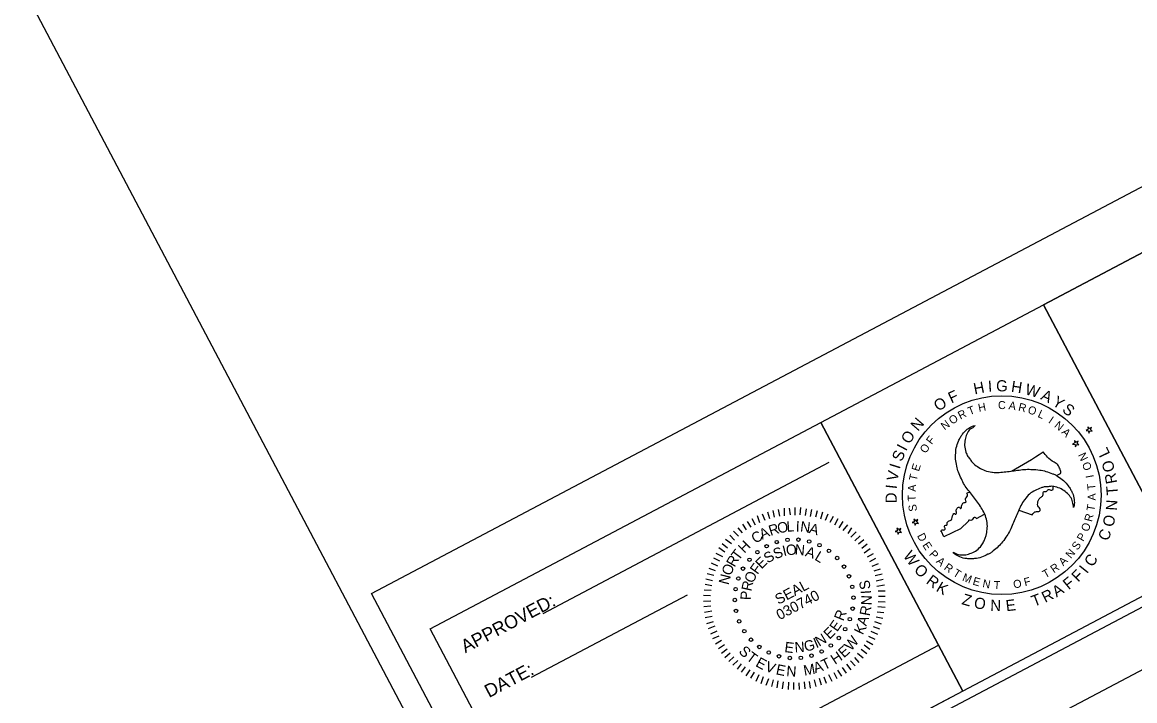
# Model space of a CAD drawing. Extents: x 1485914 to 1489436, y 493744 to 499689.
# Drawn here: x 1488661 to 1489164, y 498560 to 498867 of the extents above; entities that cross this region are included whole.
import ezdxf

# ---------------------------------------------------------------- set-up
doc = ezdxf.new("R2010")
doc.units = 0
for name, color, linetype in [('DEV BORDER CELL', 7, 'Continuous'), ('DEV DOT SWIRL SEAL CELL', 7, 'Continuous'), ('Old_Level_9', 7, 'Continuous'), ('Scratch_Level_0', 7, 'Continuous'), ('Scratch_Level_6', 7, 'Continuous'), ('Sheet Plot Border Outside CELL', 7, 'Continuous'), ('Sheet Sticker Exception Certification CELL', 7, 'Continuous'), ('Text', 7, 'Continuous'), ('WZ OSDR CELL', 7, 'Continuous')]:
    doc.layers.add(name, color=color, linetype=linetype)

msp = doc.modelspace()

# ---------------------------------------------------------------- linework, layer by layer
at = {"layer": 'DEV BORDER CELL'}
for p, q in [((1488896.29, 498599.43), (1489025.69, 498667.76)), ((1489032.96, 498665.02), (1489086.19, 498564.21)), ((1488891.04, 498570.56), (1488961.6, 498607.82))]:
    msp.add_line(p, q, dxfattribs=at)
for points in [[(1488911.97, 499654.77), (1487585.52, 498954.38), (1488075.8, 498025.87), (1489402.24, 498726.26)], [(1489331.49, 498849.23), (1489122.8, 498739.03), (1489187.01, 498617.44), (1489395.7, 498727.63)], [(1489021.99, 498685.8), (1489122.8, 498739.03), (1489187.01, 498617.44), (1489086.19, 498564.21)], [(1488845.1, 498592.4), (1489021.99, 498685.8), (1489086.19, 498564.21), (1488909.3, 498470.8)]]:
    msp.add_lwpolyline(points, close=True, dxfattribs=at)
at = {"layer": 'DEV DOT SWIRL SEAL CELL'}
for p, q in [((1489142.96, 498682.73), (1489142, 498682.22)), ((1489143.56, 498683.05), (1489142.77, 498683.77)), ((1489142.77, 498683.77), (1489142.96, 498682.73)), ((1489144.52, 498683.56), (1489143.56, 498683.05)), ((1489144.04, 498682.57), (1489144.52, 498683.56)), ((1489144.81, 498681.8), (1489144.04, 498682.57)), ((1489137.48, 498676.85), (1489136.69, 498677.56)), ((1489136.69, 498677.56), (1489136.87, 498676.53)), ((1489142, 498682.22), (1489143.08, 498682.07)), ((1489143.08, 498682.07), (1489143.28, 498681)), ((1489143.28, 498681), (1489143.73, 498681.96)), ((1489143.73, 498681.96), (1489144.81, 498681.8)), ((1489136.87, 498676.53), (1489135.91, 498676.02)), ((1489135.91, 498676.02), (1489136.99, 498675.87)), ((1489136.99, 498675.87), (1489137.2, 498674.79)), ((1489137.2, 498674.79), (1489137.64, 498675.75)), ((1489138.43, 498677.35), (1489137.48, 498676.85)), ((1489137.64, 498675.75), (1489138.72, 498675.6)), ((1489137.95, 498676.37), (1489138.43, 498677.35)), ((1489138.72, 498675.6), (1489137.95, 498676.37)), ((1489092.36, 498642.39), (1489096.1, 498644.33)), ((1489111.56, 498646.17), (1489117.55, 498644.06)), ((1489057.21, 498637.29), (1489056.42, 498638.01)), ((1489056.42, 498638.01), (1489056.61, 498636.98)), ((1489058.17, 498637.8), (1489057.21, 498637.29)), ((1489057.69, 498636.82), (1489058.17, 498637.8)), ((1489057.69, 498636.82), (1489058.17, 498637.8)), ((1489064.29, 498641.02), (1489063.33, 498640.51)), ((1489063.33, 498640.51), (1489064.41, 498640.35)), ((1489064.89, 498641.33), (1489064.1, 498642.05)), ((1489064.1, 498642.05), (1489064.29, 498641.02)), ((1489064.41, 498640.35), (1489064.61, 498639.28)), ((1489064.61, 498639.28), (1489065.06, 498640.24)), ((1489065.85, 498641.84), (1489064.89, 498641.33)), ((1489065.06, 498640.24), (1489066.14, 498640.09)), ((1489065.37, 498640.86), (1489065.85, 498641.84)), ((1489066.14, 498640.09), (1489065.37, 498640.86)), ((1489085.23, 498637.66), (1489077.66, 498634.02)), ((1489088.82, 498641.16), (1489085.23, 498637.66)), ((1489056.61, 498636.98), (1489055.65, 498636.47)), ((1489055.65, 498636.47), (1489056.73, 498636.31)), ((1489056.73, 498636.31), (1489056.93, 498635.24)), ((1489056.93, 498635.24), (1489057.38, 498636.2)), ((1489057.38, 498636.2), (1489058.46, 498636.05)), ((1489057.38, 498636.2), (1489058.46, 498636.05)), ((1489058.46, 498636.05), (1489057.69, 498636.82)), ((1489058.46, 498636.05), (1489057.69, 498636.82)), ((1489077.66, 498634.02), (1489076.5, 498636.41))]:
    msp.add_line(p, q, dxfattribs=at)
for start, end in [(299.0386, 303.1587), (293.5136, 293.8113)]:
    msp.add_arc((1488995.05, 498867.66), 233.19, start, end, dxfattribs=at)
for points in [[(1489081.81, 498627.04), (1489084.3, 498626.08), (1489086.87, 498625.86), (1489089.38, 498626.45), (1489091.95, 498627.63), (1489094.18, 498629.56), (1489095.41, 498631.3), (1489095.82, 498632.25), (1489096.54, 498633.88), (1489096.92, 498635.29), (1489097.29, 498638.15), (1489097.12, 498641.23), (1489096.11, 498644.3), (1489096, 498644.55), (1489094.58, 498647.2), (1489092.8, 498649.69), (1489091.06, 498652.08), (1489089.17, 498654.51), (1489087.34, 498656.94), (1489085.92, 498659.51), (1489084.52, 498662.56), (1489083.61, 498665.33), (1489083.06, 498668.38), (1489082.86, 498669.85), (1489082.95, 498671.17), (1489083.25, 498674.33), (1489084.27, 498677.3), (1489085.07, 498679), (1489085.98, 498680.33), (1489086.13, 498680.56), (1489088.22, 498682.7), (1489090.64, 498684.1), (1489091.58, 498684.32)], [(1489091.61, 498684.43), (1489091.58, 498684.32), (1489089.53, 498682.69), (1489088.03, 498680.53), (1489087.29, 498678.08), (1489087.03, 498675.3), (1489087.6, 498672.38), (1489088.47, 498670.44), (1489089.11, 498669.63), (1489090.15, 498668.17), (1489091.16, 498667.13), (1489093.49, 498665.41), (1489096.21, 498664), (1489099.41, 498663.35), (1489099.67, 498663.31), (1489102.64, 498663.2), (1489105.73, 498663.5), (1489108.65, 498663.83), (1489111.68, 498664.25), (1489114.72, 498664.57), (1489117.66, 498664.54), (1489121, 498664.25), (1489123.84, 498663.65), (1489126.75, 498662.61), (1489128.15, 498662.04), (1489129.24, 498661.28), (1489131.84, 498659.47), (1489133.89, 498657.09), (1489134.98, 498655.54), (1489135.69, 498654.09), (1489135.81, 498653.85), (1489136.58, 498650.95), (1489136.57, 498648.15), (1489136.32, 498647.26)], [(1489128.57, 498661.77), (1489130.61, 498663.19), (1489130.03, 498665.09), (1489129.28, 498666.55), (1489127.5, 498667.75), (1489124.53, 498670.11), (1489122.59, 498672.45)], [(1489076.5, 498636.41), (1489076.3, 498636.6), (1489076.57, 498637.06), (1489077.91, 498637.19), (1489078.21, 498637.95), (1489077.93, 498638.41), (1489078.13, 498639.13), (1489078.96, 498639.37), (1489079.19, 498640.58), (1489079.72, 498641.08), (1489081.04, 498641.78), (1489081.79, 498644.19), (1489082.38, 498644.63), (1489082.78, 498644.3), (1489083.22, 498644.43), (1489083.24, 498646.1), (1489083.32, 498646.37), (1489084.25, 498647.5), (1489084.71, 498647.43), (1489085.11, 498646.9), (1489085.34, 498646.9), (1489085.6, 498647.38), (1489085.78, 498648.37), (1489086.5, 498649.42), (1489087.73, 498649.88), (1489087.42, 498650.94), (1489088.3, 498652.55), (1489088.29, 498653.24), (1489088.07, 498653.83)], [(1489136.32, 498647.26), (1489135.92, 498649.84), (1489134.83, 498652.21), (1489133.04, 498654.09), (1489130.76, 498655.71), (1489127.98, 498656.67), (1489125.86, 498656.88), (1489124.82, 498656.73), (1489123.07, 498656.6), (1489121.61, 498656.19), (1489118.98, 498655.07), (1489116.38, 498653.4), (1489114.24, 498650.96), (1489114.07, 498650.75), (1489112.51, 498648.2), (1489111.21, 498645.42), (1489110, 498642.71), (1489108.86, 498639.87), (1489107.65, 498637.04), (1489106.15, 498634.54), (1489104.2, 498631.79), (1489102.27, 498629.64), (1489099.92, 498627.65), (1489098.72, 498626.71), (1489097.53, 498626.14), (1489094.68, 498624.82), (1489091.57, 498624.21), (1489089.71, 498624.05), (1489088.09, 498624.19), (1489087.81, 498624.2), (1489084.92, 498624.95), (1489082.52, 498626.35), (1489081.81, 498627.04)], [(1489117.55, 498644.06), (1489118.81, 498645.3), (1489120.31, 498645.48), (1489120.96, 498645.7), (1489121.27, 498646.34), (1489120.12, 498648.13), (1489120.09, 498649.23), (1489121.32, 498651.8), (1489122.43, 498652.74), (1489122.74, 498654.37), (1489123.13, 498654.55), (1489123.88, 498654.52), (1489125.02, 498655.45), (1489126.48, 498655.16), (1489127.05, 498655.53), (1489127.04, 498656.72)], [(1489092.36, 498642.39), (1489091.75, 498642.8), (1489091.06, 498642.66), (1489090.46, 498641.8), (1489089.85, 498641.51), (1489088.91, 498641.65), (1489088.82, 498641.16)]]:
    msp.add_spline(points, degree=3, dxfattribs=at)
at = {"layer": 'Old_Level_9'}
for p, q in [((1489010.12, 498647.25), (1489010.2, 498643.9)), ((1489012.81, 498647.25), (1489012.43, 498643.95)), ((1488990.77, 498642.4), (1488992.29, 498639.53)), ((1488993.09, 498643.63), (1488994.28, 498640.58)), ((1488995.37, 498644.41), (1488996.55, 498641.64)), ((1488997.86, 498645.3), (1488998.71, 498642.36)), ((1489000.2, 498645.97), (1489000.83, 498642.91)), ((1489002.65, 498646.41), (1489003.28, 498643.35)), ((1489005.32, 498646.98), (1489005.39, 498643.62)), ((1489007.67, 498647.08), (1489008.01, 498644.02)), ((1489015.33, 498646.75), (1489014.84, 498643.67)), ((1489017.8, 498646.36), (1489017.2, 498643.21)), ((1489020.33, 498645.86), (1489019.61, 498642.93)), ((1489022.64, 498645.24), (1489021.76, 498642.09)), ((1489025.12, 498644.28), (1489023.95, 498641.41)), ((1489027.49, 498643.27), (1489025.98, 498640.5)), ((1488984.38, 498638.18), (1488986.33, 498635.82)), ((1488986.53, 498639.74), (1488988.15, 498637.2)), ((1488988.57, 498640.96), (1488990.3, 498638.48)), ((1489029.64, 498642.15), (1489028.13, 498639.38)), ((1489031.85, 498640.91), (1489030.17, 498638.19)), ((1489034, 498639.51), (1489031.99, 498636.89)), ((1489035.88, 498638.09), (1489034.15, 498635.48)), ((1488978.79, 498632.97), (1488981.52, 498631.02)), ((1488980.76, 498634.86), (1488982.94, 498632.61)), ((1488982.51, 498636.63), (1488984.75, 498634.28)), ((1489037.99, 498636.24), (1489035.58, 498633.84)), ((1489039.76, 498634.49), (1489037.41, 498632.26)), ((1489041.42, 498632.68), (1489038.95, 498630.67)), ((1488975.86, 498629.16), (1488978.58, 498627.21)), ((1488977.38, 498631.09), (1488979.72, 498629.08)), ((1489042.86, 498630.76), (1489040.5, 498628.8)), ((1489044.31, 498628.55), (1489041.61, 498626.7)), ((1488972.26, 498622.31), (1488975.26, 498620.92)), ((1488973.33, 498624.57), (1488976.16, 498623.24)), ((1488974.46, 498626.72), (1488977.4, 498625.17)), ((1489045.65, 498626.29), (1489042.88, 498624.83)), ((1489046.76, 498624.19), (1489043.99, 498622.73)), ((1488970.58, 498617.47), (1488973.56, 498616.64)), ((1488971.25, 498619.94), (1488974.13, 498618.78)), ((1489047.87, 498621.81), (1489045.1, 498620.63)), ((1489048.88, 498619.37), (1489045.93, 498618.52)), ((1489049.65, 498617.09), (1489046.48, 498616.41)), ((1488969.57, 498612.69), (1488972.6, 498612.03)), ((1488969.85, 498615.1), (1488972.94, 498614.33)), ((1489050.21, 498614.7), (1489047.04, 498614.02)), ((1489050.71, 498612.14), (1489047.31, 498611.62)), ((1488968.84, 498607.64), (1488972.03, 498607.49)), ((1488969.12, 498610.05), (1488972.31, 498609.9)), ((1489051, 498609.46), (1489047.86, 498609.51)), ((1489051.1, 498607.12), (1489048.03, 498607.05)), ((1488968.84, 498604.96), (1488972.2, 498605.03)), ((1488969.01, 498602.5), (1488972.25, 498602.8)), ((1489051.05, 498602.14), (1489047.69, 498602.35)), ((1489051.11, 498604.43), (1489047.86, 498604.7)), ((1488969.24, 498599.93), (1488972.58, 498600.57)), ((1488969.68, 498597.48), (1488972.85, 498598.17)), ((1489050.04, 498597.09), (1489047.01, 498597.75)), ((1489050.54, 498599.61), (1489047.4, 498599.93)), ((1488970.35, 498594.87), (1488973.41, 498595.78)), ((1488971.13, 498592.6), (1488974.07, 498593.72)), ((1489048.64, 498592.25), (1489045.82, 498593.3)), ((1489049.43, 498594.5), (1489046.33, 498595.55)), ((1488972.14, 498590.16), (1488975.07, 498591.57)), ((1488973.13, 498588), (1488976.01, 498589.24)), ((1488974.36, 498585.68), (1488977.01, 498587.36)), ((1489046.56, 498587.61), (1489043.73, 498588.95)), ((1489047.8, 498589.82), (1489044.69, 498591.15)), ((1488975.64, 498583.53), (1488978.34, 498585.38)), ((1488977.03, 498581.43), (1488979.56, 498583.33)), ((1489042.79, 498581.1), (1489040.17, 498583.11)), ((1489044.14, 498583.09), (1489041.59, 498584.99)), ((1489045.55, 498585.24), (1489042.61, 498586.8)), ((1488978.53, 498579.4), (1488980.94, 498581.52)), ((1488980.3, 498577.65), (1488982.6, 498579.71)), ((1488982.18, 498575.95), (1488984.42, 498578.13)), ((1489037.49, 498575.62), (1489035.42, 498577.92)), ((1489039.35, 498577.17), (1489037.29, 498579.47)), ((1489041.16, 498579.11), (1489038.59, 498581.29)), ((1488984.23, 498574.21), (1488986.08, 498576.6)), ((1488986.11, 498572.8), (1488987.9, 498575.3)), ((1488988.21, 498571.22), (1488990.05, 498573.89)), ((1488990.25, 498570.04), (1488991.92, 498572.76)), ((1488992.74, 498568.81), (1488994.02, 498571.74)), ((1489029.4, 498569.79), (1489027.94, 498572.55)), ((1489031.44, 498571.01), (1489029.7, 498573.77)), ((1489033.53, 498572.4), (1489031.8, 498574.87)), ((1489035.68, 498573.95), (1489033.67, 498576.43)), ((1488995, 498567.74), (1488996.05, 498570.84)), ((1488997.25, 498566.95), (1488998.36, 498569.94)), ((1488999.84, 498566.34), (1489000.5, 498569.37)), ((1489002.15, 498565.72), (1489002.69, 498568.97)), ((1489004.67, 498565.21), (1489005.1, 498568.41)), ((1489007.3, 498565.05), (1489007.46, 498568.24)), ((1489009.77, 498564.94), (1489009.75, 498568.18)), ((1489012.28, 498564.99), (1489012.21, 498568.07)), ((1489014.85, 498565.22), (1489014.55, 498568.45)), ((1489017.36, 498565.55), (1489016.84, 498568.67)), ((1489019.91, 498566.34), (1489019.06, 498569.28)), ((1489022.3, 498566.89), (1489021.4, 498569.95)), ((1489024.58, 498567.67), (1489023.51, 498570.5)), ((1489027.02, 498568.67), (1489025.61, 498571.61))]:
    msp.add_line(p, q, dxfattribs=at)
for centre in [(1489002.01, 498631.67), (1489006.87, 498632.68), (1489011.82, 498632.78), (1489016.71, 498631.96), (1488993.26, 498627.09), (1488997.43, 498629.79), (1489021.37, 498630.26), (1489025.64, 498627.74), (1488989.67, 498623.68), (1489029.36, 498624.47), (1488986.76, 498619.67), (1489032.43, 498620.58), (1488984.64, 498615.19), (1489034.73, 498616.19), (1489036.18, 498611.45), (1488983.38, 498610.39), (1489036.73, 498606.52), (1488983.02, 498605.45), (1489036.37, 498601.58), (1488983.58, 498600.53), (1489035.11, 498596.78), (1488985.03, 498595.79), (1488987.33, 498591.39), (1489032.99, 498592.3), (1488990.39, 498587.5), (1489030.08, 498588.29), (1488994.12, 498584.23), (1488998.39, 498581.71), (1489022.33, 498582.19), (1489026.49, 498584.88), (1489003.04, 498580.01), (1489007.93, 498579.2), (1489012.89, 498579.3), (1489017.74, 498580.3)]:
    msp.add_circle(centre, 0.788, dxfattribs=at)
at = {"layer": 'Scratch_Level_0'}
msp.add_lwpolyline([(1488891.1, 499587.21), (1487653.08, 498933.51), (1488096.67, 498093.43), (1488873.83, 498503.79), (1488818.61, 498608.38), (1489279.46, 498851.72)], close=True, dxfattribs=at)
at = {"layer": 'Scratch_Level_6'}
msp.add_lwpolyline([(1489122.8, 498739.03), (1489331.49, 498849.23), (1489395.7, 498727.63), (1489187.01, 498617.44)], close=True, dxfattribs=at)
at = {"layer": 'Sheet Plot Border Outside CELL'}
msp.add_lwpolyline([(1487943.33, 497927.66), (1489436.02, 498715.83), (1488922.4, 499688.55), (1487429.71, 498900.38)], close=True, dxfattribs=at)
at = {"layer": 'Sheet Sticker Exception Certification CELL'}
for p, q in [((1488898.33, 498491.59), (1489075.22, 498584.99)), ((1489075.23, 498584.98), (1489086.2, 498564.2)), ((1489086.19, 498564.21), (1488909.3, 498470.8))]:
    msp.add_line(p, q, dxfattribs=at)
at = {"layer": 'Text'}
msp.add_circle((1489103.82, 498652.91), 44.97, dxfattribs=at)
at = {"layer": 'WZ OSDR CELL'}
msp.add_lwpolyline([(1487648.11, 498943.96), (1488414.63, 499348.7), (1488845.5, 498532.69), (1488078.98, 498127.95)], close=True, dxfattribs=at)

# ---------------------------------------------------------------- texts
at = {"layer": 'DEV BORDER CELL'}
for s, p in [('APPROVED:  ', (1488861.08, 498581.33)), ('DATE:  ', (1488871.78, 498561.07))]:
    msp.add_text(s, height=6, rotation=27.8351, dxfattribs=at).set_placement(p)
at = {"layer": 'DEV DOT SWIRL SEAL CELL'}
for s, height, rotation, p in [('H', 5.04, 11.2891, (1489091.58, 498698.45)), ('I', 5.04, 3.6391, (1489097.75, 498699.6)), ('G', 5.04, 359.3518, (1489101.26, 498699.88)), ('H', 5.04, 351.2983, (1489107.86, 498699.7)), ('W', 5.04, 343.6484, (1489114.05, 498698.66)), ('F', 5.04, 25.0926, (1489081.04, 498694.35)), ('A', 5.04, 334.6113, (1489121.11, 498696.4)), ('Y', 5.04, 327.5835, (1489126.3, 498693.88)), ('O', 5.04, 33.6, (1489075.15, 498690.61)), ('H', 3.63, 11.4673, (1489093.53, 498690.53)), ('C', 3.63, 1.3112, (1489102.18, 498691.8)), ('A', 3.63, 351.155, (1489106.79, 498691.83)), ('R', 3.63, 346.0769, (1489111.08, 498691.2)), ('O', 3.63, 340.9988, (1489115.27, 498690.12)), ('S', 5.04, 321.06, (1489130.81, 498691)), ('N', 5.04, 49.4212, (1489065.93, 498681.52)), ('O', 3.63, 31.7797, (1489081.28, 498684.72)), ('R', 3.63, 26.7016, (1489085.11, 498687.06)), ('L', 3.63, 335.9207, (1489119.83, 498688.38)), ('I', 3.63, 325.7646, (1489124.63, 498685.82)), ('N', 3.63, 36.8577, (1489077.95, 498682.15)), ('N', 3.63, 320.6865, (1489127.33, 498683.96)), ('A', 3.63, 315.6084, (1489130.64, 498681.12)), ('O', 5.04, 57.9286, (1489062.1, 498675.69)), ('F', 3.63, 52.092, (1489072.13, 498675.56)), ('S', 5.04, 68.4199, (1489058.63, 498667.81)), ('I', 5.04, 62.2159, (1489060.51, 498672.55)), ('O', 3.63, 57.1701, (1489069.51, 498671.51)), ('N', 3.63, 115.5681, (1489143.06, 498669.49)), ('O', 3.63, 110.762, (1489144.78, 498664.89)), ('V', 5.04, 79.4157, (1489056.6, 498659.03)), ('I', 5.04, 72.7073, (1489057.64, 498664.44)), ('T', 3.63, 77.4824, (1489065.33, 498659.14)), ('E', 3.63, 72.4043, (1489066.32, 498663.4)), ('I', 5.04, 83.703, (1489056.27, 498655.53)), ('A', 3.63, 87.6386, (1489064.93, 498654.42)), ('I', 3.63, 100.6058, (1489145.57, 498661.06)), ('T', 3.63, 95.5277, (1489146.33, 498655.36)), ('D', 5.04, 91.2941, (1489056.34, 498649.3)), ('T', 3.63, 92.7167, (1489064.99, 498650.16)), ('A', 3.63, 90.4496, (1489146.38, 498650.48)), ('S', 3.63, 97.7948, (1489065.52, 498645.75)), ('T', 3.63, 80.2935, (1489145.71, 498645.44)), ('R', 3.63, 75.2154, (1489144.58, 498640.61)), ('O', 3.63, 70.1373, (1489142.98, 498636.08)), ('D', 3.63, 298.1071, (1489065.39, 498634.54)), ('P', 3.63, 59.9811, (1489140.69, 498631.68)), ('E', 3.63, 303.1852, (1489067.77, 498630.3)), ('P', 3.63, 313.3414, (1489070.73, 498625.98)), ('N', 3.63, 49.825, (1489135.09, 498624)), ('S', 3.63, 54.903, (1489138.12, 498627.72)), ('A', 3.63, 318.4194, (1489073.87, 498622.6)), ('R', 3.63, 323.4975, (1489077.38, 498619.54)), ('A', 3.63, 44.7469, (1489131.69, 498620.63)), ('T', 3.63, 328.5756, (1489081.45, 498616.71)), ('M', 3.63, 338.7318, (1489085.68, 498614.31)), ('T', 3.63, 29.5126, (1489123.55, 498615.18)), ('R', 3.63, 34.5907, (1489127.41, 498617.49)), ('E', 3.63, 343.8099, (1489090.41, 498612.5)), ('N', 3.63, 348.8879, (1489094.91, 498611.3)), ('T', 3.63, 359.0441, (1489100.18, 498610.42)), ('O', 3.63, 9.2003, (1489109.32, 498610.7)), ('F', 3.63, 14.2784, (1489114.36, 498611.69))]:
    msp.add_text(s, height=height, rotation=rotation, dxfattribs=at).set_placement(p)
at = {"layer": 'Old_Level_9'}
for s, height, rotation, p in [('A', 4.72, 25.81, (1488995.46, 498632.72)), ('R', 4.72, 17.8566, (1488999.22, 498634.43)), ('O', 4.72, 10.9219, (1489002.72, 498635.57)), ('L', 4.72, 3.581, (1489006.56, 498636.32)), ('I', 4.72, 358.641, (1489010.59, 498636.47)), ('N', 4.72, 352.7389, (1489012.43, 498636.45)), ('A', 4.72, 344.8402, (1489016.3, 498635.81)), ('H', 4.72, 45.5784, (1488987.38, 498626.34)), ('C', 4.72, 32.775, (1488992.37, 498630.81)), ('T', 4.72, 53.2709, (1488984.77, 498622.98)), ('S', 4.7, 32.3031, (1488997.94, 498621.88)), ('S', 4.7, 20.8765, (1489001.42, 498623.85)), ('I', 4.7, 13.3172, (1489005.19, 498625.28)), ('O', 4.7, 5.71, (1489006.41, 498625.64)), ('N', 4.7, 355.2281, (1489010.03, 498626)), ('A', 4.7, 341.7789, (1489014.58, 498625.43)), ('L', 4.7, 329.3674, (1489018.81, 498623.85)), ('R', 4.72, 60.0105, (1488982.94, 498620.03)), ('F', 4.7, 54.235, (1488993.3, 498616.74)), ('E', 4.7, 44.424, (1488995.09, 498619.24)), ('N', 4.72, 75.9017, (1488980.2, 498612.09)), ('O', 4.72, 67.7793, (1488981.18, 498616.14)), ('O', 4.7, 66.0869, (1488991.32, 498612.73)), ('R', 4.7, 77.5829, (1488990.5, 498609.19)), ('SEAL', 4.699, 27.8351, (1489002.76, 498603.27)), ('S', 4.72, 100.093, (1489044.57, 498610.61)), ('P', 4.7, 87.9587, (1488990.25, 498605.38)), ('030740', 4.699, 27.8351, (1489003.34, 498596.28)), ('I', 4.72, 93.8815, (1489044.78, 498608.33)), ('N', 4.72, 87.2077, (1489044.87, 498603)), ('R', 4.72, 78.9854, (1489044.04, 498597.99)), ('R', 4.7, 68.1844, (1489032.12, 498595.68)), ('A', 4.72, 71.3568, (1489042.54, 498593.42)), ('E', 4.7, 43.6408, (1489025.87, 498587.44)), ('E', 4.7, 54.9919, (1489029.32, 498590.81)), ('K', 4.72, 63.9761, (1489040.96, 498589.38)), ('G', 4.7, 15.3163, (1489015.04, 498582)), ('I', 4.7, 23.4597, (1489019.87, 498583.56)), ('N', 4.7, 30.9629, (1489021.19, 498584.26)), ('W', 4.72, 49.8409, (1489035.68, 498582.12)), ('S', 4.72, 316.0471, (1488984.5, 498581.87)), ('T', 4.72, 323.4595, (1488987.87, 498578.68)), ('E', 4.7, 352.7043, (1489005.31, 498581.95)), ('N', 4.7, 3.8935, (1489010.23, 498581.72)), ('H', 4.72, 33.8463, (1489028.4, 498576.1)), ('E', 4.72, 41.9998, (1489032.41, 498579.04)), ('E', 4.72, 331.6576, (1488992.08, 498575.7)), ('V', 4.72, 339.7649, (1488996.44, 498573.5)), ('A', 4.72, 18.0173, (1489019.43, 498572.31)), ('T', 4.72, 25.2217, (1489023.52, 498573.68)), ('E', 4.72, 348.0663, (1489001.36, 498571.91)), ('N', 4.72, 356.1641, (1489006.24, 498571.05)), ('M', 4.72, 10.1721, (1489014.53, 498571.18))]:
    msp.add_text(s, height=height, rotation=rotation, dxfattribs=at).set_placement(p)
at = {"layer": 'Text'}
for s, height, rotation, p in [('T', 3.63, 21.6235, (1489089.31, 498689.02)), ('L', 5.04, 115.2641, (1489152.99, 498671.57)), ('O', 5.04, 106.8247, (1489155.2, 498664.16)), ('R', 5.04, 100.587, (1489156.11, 498658.51)), ('T', 5.04, 94.7161, (1489156.41, 498653.13)), ('N', 5.04, 86.7271, (1489155.93, 498645.82)), ('O', 5.04, 78.2877, (1489154.33, 498638.25)), ('C', 5.04, 70.9158, (1489152.03, 498631.89)), ('W', 5.04, 305.9851, (1489058.98, 498625.42)), ('C', 5.04, 55.8384, (1489144.9, 498620.07)), ('O', 5.04, 314.9498, (1489063.81, 498618.77)), ('F', 5.04, 45.5978, (1489138.41, 498613.29)), ('I', 5.04, 51.5854, (1489142.35, 498617.11)), ('R', 5.04, 323.3892, (1489069.26, 498613.26)), ('K', 5.04, 329.6269, (1489073.77, 498609.74)), ('A', 5.04, 32.6385, (1489128.64, 498606.54)), ('F', 5.04, 39.6102, (1489134.09, 498609.9)), ('Z', 5.04, 344.0038, (1489085.43, 498603.63)), ('T', 5.04, 20.5299, (1489118.37, 498602.36)), ('R', 5.04, 26.4007, (1489123.46, 498604.12)), ('O', 5.04, 350.3584, (1489090.99, 498601.9)), ('N', 5.04, 358.7977, (1489098.62, 498600.57)), ('E', 5.04, 6.7868, (1489105.94, 498600.35))]:
    msp.add_text(s, height=height, rotation=rotation, dxfattribs=at).set_placement(p)

doc.saveas('drawing.dxf')
